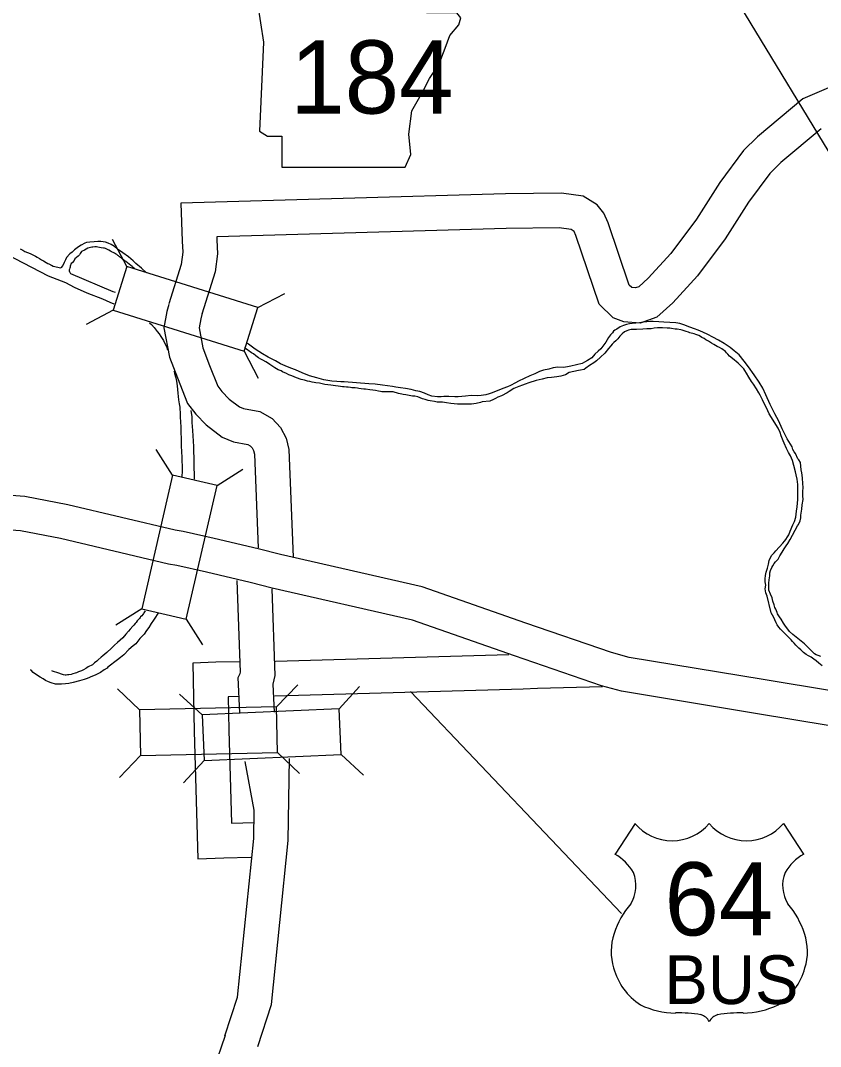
# Model space of a CAD drawing. Extents: x 1720274 to 1751788, y 372074 to 391887.
# Drawn here: x 1725014 to 1726109, y 385389 to 386793 of the extents above; entities that cross this region are included whole.
import ezdxf

# ---------------------------------------------------------------- set-up
doc = ezdxf.new("R2010")
doc.units = 0
for name, color, linetype in [('Level 10', 7, 'Continuous'), ('Level 11', 7, 'Continuous'), ('Level 15', 7, 'Continuous'), ('Level 20', 7, 'Continuous'), ('Level 21', 7, 'Continuous'), ('Level 22', 7, 'Continuous'), ('Level 9', 7, 'Continuous'), ('R_Draft', 7, 'Continuous')]:
    doc.layers.add(name, color=color, linetype=linetype)

msp = doc.modelspace()

# ---------------------------------------------------------------- linework, layer by layer
at = {"layer": 'Level 10'}
for points in [[(1726168.7, 386721.5), (1726084.8, 386685.5), (1726022.8, 386633.5), (1726003.7, 386614.7), (1725971.3, 386571.1), (1725939.5, 386521.1), (1725904, 386473.8), (1725873.4, 386440.2), (1725860.2, 386428.3), (1725856, 386426.8), (1725851, 386427.2), (1725847.2, 386430.8), (1725818.6, 386515.8), (1725812.7, 386529.2), (1725803.4, 386540.4), (1725784.3, 386552.3), (1725754.5, 386556.5), (1725677.9, 386555.5), (1725233.4, 386542.7), (1725235.5, 386490.8), (1725236.1, 386475.7), (1725234, 386458.9), (1725217.2, 386405.2)], [(1726109.9, 386644.7), (1726054.7, 386598.4), (1726039.6, 386583.5), (1726010.3, 386544.2), (1725978.5, 386494.1), (1725940.6, 386443.6), (1725906.9, 386406.6), (1725884.9, 386386.7), (1725862.2, 386378.7), (1725839.9, 386380.5), (1725825.4, 386386.1), (1725806, 386404.6), (1725774.3, 386498.7), (1725772, 386504), (1725771.9, 386504.2), (1725767.7, 386506.8), (1725751.5, 386509), (1725678.9, 386508.1), (1725282.7, 386496.7), (1725282.8, 386492.8), (1725283.6, 386473.7), (1725280.5, 386448.8), (1725262.5, 386391.1)], [(1725217, 386404.2), (1725214.4, 386394.7), (1725210.5, 386372.1), (1725218, 386332.1), (1725228.8, 386303.6), (1725242.6, 386268.5), (1725254, 386254.1), (1725268.2, 386239.3), (1725290.2, 386222.5), (1725305.6, 386216.1), (1725325.3, 386212.5), (1725328.7, 386210.6), (1725331, 386208.1), (1725333.1, 386204.2), (1725334.2, 386199.3), (1725339.4, 386071.2)], [(1725262.8, 386392.1), (1725260.8, 386384.6), (1725258.7, 386372.4), (1725263.8, 386345), (1725273, 386320.6), (1725284.1, 386292.4), (1725289.8, 386285.3), (1725299.8, 386274.8), (1725314.1, 386263.9), (1725319.2, 386261.8), (1725341.7, 386257.6), (1725358.6, 386248.2), (1725370.1, 386235.6), (1725377.8, 386221.1), (1725381.4, 386205.8), (1725387.3, 386058.5)], [(1725314.3, 385845.4), (1725312.1, 385893.6), (1725314.7, 385899.2), (1725315.1, 385901), (1725310.9, 386026.4)], [(1725361.7, 385846.4), (1725360, 385884.7), (1725362.7, 385896.4), (1725358.7, 386015.1)], [(1725251.8, 385820.2), (1725256.7, 385645.5), (1725292.4, 385646.7), (1725329.6, 385647.6)], [(1725299.2, 385821.6), (1725302.8, 385694.3), (1725333.9, 385695.1)], [(1725339.1, 385388.8), (1725357.7, 385446.2), (1725380.7, 385670.6), (1725382.4, 385782.8)], [(1725294, 385403.4), (1725311.1, 385456), (1725333.3, 385673.4), (1725333.9, 385711.9), (1725321.8, 385778.9)], [(1725294.1, 385403.7), (1725278.4, 385357.1), (1725275.9, 385321.8), (1725286.6, 385031.4), (1725290.2, 384925.1), (1725291.3, 384893.1)]]:
    msp.add_lwpolyline(points, dxfattribs=at)
at = {"layer": 'Level 11'}
for points in [[(1725314.4, 385914.9), (1725281.3, 385914.5), (1725249.8, 385913.5), (1725251.8, 385820.4)], [(1725312.9, 385867.5), (1725298.2, 385867.3), (1725299.2, 385821.4)]]:
    msp.add_lwpolyline(points, dxfattribs=at)
at = {"layer": 'Level 15'}
for points in [[(1726544.9, 385908.9), (1726538.4, 385906.8), (1726379.3, 385861.8), (1726334.7, 385854.1), (1726286.7, 385852.8), (1726253, 385855.1), (1726127, 385874.8), (1726030.6, 385890.8), (1725847, 385921.2), (1725823.1, 385927.7), (1725705.9, 385968.2), (1725564, 386017.9), (1725369.9, 386062.2), (1725339.5, 386069.8), (1725279.4, 386083.9), (1725236.8, 386093.7), (1725225.7, 386095.4), (1725079.1, 386130.1), (1725020.3, 386141.6), (1724975.9, 386144.7), (1724941.7, 386143.1), (1724848.3, 386134.7)], [(1726545.5, 385859.6), (1726389.8, 385815.5), (1726339.3, 385806.8), (1726285.7, 385805.4), (1726247.7, 385808), (1726119.5, 385828), (1726022.9, 385844), (1725836.8, 385874.8), (1725809.1, 385882.4), (1725690.3, 385923.4), (1725550.8, 385972.3), (1725358.8, 386016.1), (1725328.4, 386023.7), (1725268.6, 386037.7), (1725227.9, 386047.1), (1725216.7, 386048.8), (1725069.1, 386083.8), (1725014.1, 386094.5), (1724975.3, 386097.3), (1724944.9, 386095.8), (1724852.6, 386087.5)], [(1725363.2, 385916), (1725682.4, 385925.1)], [(1725362.1, 385868.5), (1725702.3, 385878.3), (1725721.6, 385879.1), (1725810.8, 385881.2)]]:
    msp.add_lwpolyline(points, dxfattribs=at)
at = {"layer": 'Level 20'}
for p, q in [((1725159.6, 386456), (1725140.2, 386492.9)), ((1725338.8, 386400), (1725375.7, 386419.4)), ((1725141, 386396.2), (1725104, 386376.9)), ((1725320.1, 386340.3), (1725339.5, 386303.4)), ((1725222.1, 386170.5), (1725200, 386205.9)), ((1725283.1, 386156.5), (1725318.4, 386178.7)), ((1725222.1, 386170.5), (1725180.1, 385987.6)), ((1725283.1, 386156.5), (1725222.1, 386170.5)), ((1725241, 385973.6), (1725283.1, 386156.5)), ((1725180.1, 385987.6), (1725144.7, 385965.5)), ((1725180.1, 385987.6), (1725241, 385973.6)), ((1725241, 385973.6), (1725263.2, 385938.2)), ((1725364.7, 385853.5), (1725393.5, 385883.6)), ((1725450.1, 385850.8), (1725478.3, 385881.5)), ((1725177, 385849.4), (1725146.9, 385878.2)), ((1725262.6, 385842.5), (1725231.9, 385870.7)), ((1725178.4, 385786.8), (1725149.6, 385756.7)), ((1725366.1, 385791), (1725396.2, 385762.1)), ((1725452.9, 385788.3), (1725483.7, 385760.1)), ((1725265.4, 385780), (1725237.2, 385749.3))]:
    msp.add_line(p, q, dxfattribs=at)
for points in [[(1725338.8, 386400), (1725159.6, 386456), (1725141, 386396.2), (1725320.1, 386340.3)], [(1725364.7, 385853.5), (1725177, 385849.4), (1725178.4, 385786.8), (1725366.1, 385791)], [(1725450.1, 385850.8), (1725262.6, 385842.5), (1725265.4, 385780), (1725452.9, 385788.3)]]:
    msp.add_lwpolyline(points, close=True, dxfattribs=at)
at = {"layer": 'Level 21'}
msp.add_lwpolyline([(1725334.6, 386843.2), (1725346.6, 386763), (1725341.3, 386641.3), (1725352, 386634.7), (1725372, 386634.7), (1725372, 386591.9), (1725540.4, 386591.9), (1725548.5, 386609.3), (1725545.8, 386637.3), (1725549.8, 386669.4), (1725564.5, 386694.8), (1725573.9, 386713.5), (1725587.2, 386733.6), (1725595.2, 386755), (1725601.9, 386772.3), (1725614, 386787), (1725616.6, 386796.4), (1725611.3, 386803.1), (1725569.8, 386803.1), (1725579.2, 386821.8), (1725580.5, 386833.8), (1725575, 386843)], close=True, dxfattribs=at)
at = {"layer": 'Level 22'}
for p, q in [((1725547.8, 385874.3), (1725836.9, 385570.7)), ((1725855.2, 385694), (1725827.8, 385651.8)), ((1726058.5, 385694), (1726085.8, 385651.8))]:
    msp.add_line(p, q, dxfattribs=at)
for centre, radius, start, end in [((1725906.1, 385736.9), 66.6, 220.075, 319.6701), ((1726007.6, 385736.9), 66.6, 220.3299, 319.925), ((1725792.1, 385590.4), 71, 30.7809, 59.9883), ((1726121.6, 385590.4), 71, 120.0117, 149.2191), ((1725807.7, 385609.1), 48.7, 328.8105, 21.2108), ((1726105.9, 385609.1), 48.7, 158.7892, 211.1895), ((1725935.1, 385509.3), 113.6, 138.9565, 162.6913), ((1725978.6, 385509.3), 113.6, 17.3087, 41.0435), ((1725897.6, 385518.6), 75.1, 160.9576, 197.3819), ((1726016.1, 385518.6), 75.1, 342.6181, 19.0424), ((1725909.8, 385518.8), 86.9, 195.1074, 237.1312), ((1726003.9, 385518.8), 86.9, 302.8688, 344.8926), ((1725911.4, 385546.1), 111.6, 244.0771, 269.5779), ((1726002.2, 385546.1), 111.6, 270.4221, 295.9229), ((1725914, 385230.3), 204.3, 81.1942, 90.9539), ((1725939.5, 385413.5), 19.6, 28.0342, 72.9864), ((1725974.1, 385413.5), 19.6, 107.0136, 151.9658), ((1725999.7, 385230.3), 204.3, 89.0461, 98.8058)]:
    msp.add_arc(centre, radius, start, end, dxfattribs=at)
at = {"layer": 'Level 9'}
for points in [[(1724946.1, 386498.6), (1724949, 386496.8), (1725052, 386443.4), (1725075.6, 386434.3), (1725087.8, 386428), (1725105, 386420.2), (1725126.2, 386412), (1725136.5, 386407.3), (1725141.9, 386405.1)], [(1725186.8, 386447.7), (1725179.9, 386453.9), (1725172.1, 386460.3), (1725168.2, 386464.1), (1725161.9, 386469.6), (1725154.3, 386474.8), (1725147, 386479.7), (1725142.6, 386483.6), (1725138.1, 386486.4), (1725134.3, 386488.2), (1725130.3, 386489.5), (1725124.3, 386490.4), (1725119.8, 386490.4), (1725115, 386490.1), (1725109, 386489.4), (1725104.6, 386488.8), (1725102.2, 386488.1), (1725097, 386485.4), (1725093.6, 386483.1), (1725088.2, 386478.9), (1725085, 386476), (1725081.6, 386473.5), (1725077.3, 386468.4), (1725075.7, 386465.1), (1725073.8, 386461.5), (1725071.9, 386457.6), (1725069.4, 386454.4)], [(1725170.3, 386453.5), (1725169.7, 386454), (1725168.5, 386454.9), (1725167.1, 386456.3), (1725164.6, 386457.8), (1725163.4, 386458.7), (1725162.7, 386459.5), (1725160.6, 386461.2), (1725158.3, 386462.8), (1725157.3, 386463.6), (1725156.2, 386464.4), (1725153, 386466.9), (1725152.3, 386467.4), (1725149.6, 386469.4), (1725148.4, 386470.6), (1725147.5, 386471.4), (1725146, 386472.4), (1725144.4, 386473.6), (1725142.6, 386474.5), (1725141, 386475.4), (1725138.8, 386476.3), (1725137.3, 386477.2), (1725134.9, 386478.4), (1725132.3, 386479.7), (1725130.4, 386480.8), (1725129.1, 386481.1), (1725127.6, 386481.3), (1725124.5, 386481.9), (1725120.1, 386482.7), (1725118, 386483.1), (1725116.1, 386482.9), (1725113.3, 386482.6), (1725111.7, 386482.4), (1725108.3, 386481.8), (1725106.4, 386481.1), (1725104.1, 386479.9), (1725101.8, 386478.4), (1725097.7, 386476.7), (1725095.9, 386474), (1725094.7, 386472.3), (1725092.9, 386470.4), (1725090.9, 386468.6), (1725088.6, 386466.7), (1725087.4, 386464.5), (1725084.8, 386461.2), (1725083.4, 386460.1), (1725082.3, 386456.6), (1725082, 386455), (1725081.8, 386454.2), (1725081.3, 386452.6), (1725080.9, 386451.8), (1725080.8, 386451), (1725080.8, 386450), (1725081.3, 386448.9), (1725081.5, 386448.6), (1725082, 386447.4), (1725082.5, 386446.6), (1725082.8, 386446.4)], [(1725013.5, 386480.2), (1725017.3, 386478.4), (1725020.2, 386476.9), (1725023.9, 386475.3), (1725027.6, 386473.8), (1725031.1, 386472), (1725034.5, 386470.4), (1725036.9, 386469), (1725040.3, 386466.9), (1725043, 386465.4), (1725045.8, 386463.8), (1725049.3, 386461.7), (1725051.4, 386460.3), (1725052.9, 386459.6), (1725054.6, 386458.7), (1725055.3, 386458.4), (1725056.5, 386457.8), (1725058.9, 386456.7), (1725069.4, 386454.4)], [(1725082.8, 386446.4), (1725140.3, 386422.1), (1725143.5, 386421)], [(1725190.7, 386379), (1725193.5, 386376.8), (1725197.2, 386372.6), (1725201.1, 386367.4), (1725204.1, 386363.8), (1725206.2, 386360.4), (1725208.2, 386357.5), (1725209.7, 386354.8), (1725210.9, 386352.6), (1725212.5, 386349.2), (1725214.3, 386345.5), (1725215.3, 386342.1)], [(1725925, 386367.2), (1725919.8, 386368.9), (1725917.9, 386369.3), (1725912.9, 386370.4), (1725910.1, 386370.5), (1725905.2, 386371.5), (1725902.8, 386371.7), (1725899.2, 386371.9), (1725893, 386372.2), (1725890, 386372.4), (1725885.9, 386372.4), (1725881.5, 386371.8), (1725877.4, 386371), (1725871.4, 386371), (1725865.7, 386370.3), (1725857.1, 386370), (1725852.8, 386369.9), (1725849.7, 386369.8), (1725846.4, 386368.9), (1725843.9, 386367.9), (1725840.9, 386366.7), (1725837.7, 386364.2), (1725834.5, 386360.6), (1725831.6, 386357.2), (1725828.9, 386354.5), (1725826, 386352.1), (1725824.1, 386350), (1725822.1, 386347.8), (1725818.8, 386343.9), (1725813.8, 386337.6), (1725808, 386332.3), (1725802.3, 386327), (1725798.6, 386324.4), (1725792.9, 386320.6), (1725788, 386316.9), (1725785.4, 386315.4), (1725780.5, 386314.1), (1725777.7, 386313.6), (1725765.1, 386310.9), (1725760, 386308.1), (1725753.8, 386306), (1725748.3, 386305), (1725741.1, 386304.3), (1725734.8, 386303.6), (1725728, 386302), (1725719.9, 386300.1), (1725709.9, 386296.8), (1725704.8, 386294.9), (1725701.2, 386293.6), (1725696.2, 386292), (1725689.5, 386289.1), (1725683, 386285.3), (1725680.1, 386283.3), (1725672.3, 386279.2), (1725667.5, 386277.2), (1725664.1, 386275.3), (1725661.3, 386274.1), (1725656.6, 386271.9), (1725646.2, 386270.8), (1725643.7, 386269.9), (1725637.9, 386268.8), (1725631.3, 386267.9), (1725625.2, 386267.7), (1725618.7, 386267.7), (1725612.1, 386267.6), (1725603.2, 386268.7), (1725597.2, 386269.8), (1725591.8, 386270.3), (1725584.5, 386270.7), (1725580.9, 386271.3), (1725574.8, 386272.2), (1725572.1, 386272.8), (1725567.8, 386274.1), (1725564.5, 386275.1), (1725558.1, 386278), (1725553.8, 386278.7), (1725550.8, 386278.9), (1725541.6, 386280.7), (1725538.1, 386281), (1725536, 386281.4), (1725531.7, 386282.3), (1725524.2, 386284.5), (1725512.6, 386284.5), (1725510.7, 386284.7), (1725508.9, 386284.8), (1725506.9, 386284.9), (1725504.2, 386285.5), (1725500, 386286.5), (1725496.5, 386287), (1725492.1, 386287.3), (1725486.3, 386288.1), (1725484.2, 386288.3), (1725480.2, 386288.8), (1725477.4, 386289.2), (1725475.5, 386289.6), (1725472.3, 386290), (1725470.2, 386290.1), (1725467.6, 386290.3), (1725465.7, 386290.6), (1725462.5, 386290.8), (1725460.1, 386291)], [(1726045.8, 386049.7), (1726047.4, 386051.9), (1726051.1, 386055.4), (1726053.6, 386060.2), (1726056.6, 386065.4), (1726059.3, 386069.8), (1726061.9, 386074), (1726064.4, 386077.2), (1726067.6, 386082.7), (1726077.7, 386101.1), (1726078.7, 386103), (1726081.1, 386108), (1726082.2, 386112), (1726082.2, 386115.8), (1726083.4, 386124), (1726084.1, 386129.8), (1726085.2, 386137.2), (1726085, 386142.2), (1726084.8, 386147.8), (1726085.1, 386154.3), (1726084.7, 386158.9), (1726084.5, 386167), (1726083.3, 386173.7), (1726082.7, 386177.7), (1726081.6, 386187.8), (1726079.4, 386191.7), (1726078.2, 386193.1), (1726074.7, 386200.1), (1726073, 386202.4), (1726071, 386205.7), (1726070.1, 386209.3), (1726067.9, 386213.2), (1726063.3, 386220.5), (1726056.7, 386234), (1726051.9, 386244.5), (1726046.7, 386254.6), (1726040.3, 386267.4), (1726034.3, 386280.6), (1726029.9, 386289.6), (1726025.3, 386298), (1726018.4, 386307.9), (1726010.6, 386318.9), (1726004.7, 386326.8), (1725997.7, 386335.3), (1725990.8, 386340.8), (1725985.3, 386345.2), (1725977.2, 386351), (1725969.3, 386355.3), (1725961.9, 386359.5), (1725955, 386363.1), (1725947.8, 386366.2), (1725941.7, 386369), (1725936.4, 386370.7), (1725930.2, 386373.2), (1725922.2, 386376.4), (1725916.6, 386378.3), (1725911.2, 386379.1), (1725902.8, 386379.5), (1725894.8, 386379.8), (1725888, 386380.4), (1725880.2, 386380.8), (1725875.7, 386381), (1725867, 386380), (1725861.5, 386379.2), (1725856.5, 386378.4), (1725851.1, 386378.1), (1725847.7, 386377.5), (1725843.6, 386376.9), (1725839.5, 386375.3), (1725835, 386373.4), (1725830.2, 386370.6), (1725827.4, 386369.2), (1725825.8, 386367.6), (1725824.2, 386365.3), (1725821.8, 386362.6), (1725818.8, 386358.8), (1725815.4, 386352.8), (1725811, 386347.1), (1725808.2, 386343.7), (1725804.7, 386340.4), (1725800.4, 386336.3), (1725795.9, 386331.3), (1725790.2, 386327.6), (1725786.1, 386325.3), (1725782.9, 386323.2), (1725767.2, 386319.7), (1725762.8, 386318.8), (1725757.2, 386318.1), (1725749.6, 386318.2), (1725743, 386317.3), (1725737.4, 386315.7), (1725729.8, 386314.4), (1725724.4, 386312.3), (1725718.3, 386309.4), (1725711.2, 386306.5), (1725703.6, 386302.7), (1725695.9, 386299.3), (1725691.6, 386297), (1725684.6, 386293.4), (1725680.6, 386291.5), (1725674.5, 386289.4)], [(1726077.8, 385935.3), (1726075.2, 385937.9), (1726073.1, 385940.7), (1726070.8, 385942.9), (1726068.8, 385945), (1726066.9, 385947), (1726065.2, 385948.9), (1726062.9, 385951.2), (1726060.5, 385953.6), (1726057.7, 385956.4), (1726054.5, 385959.6), (1726052, 385962.7), (1726049.8, 385965.9), (1726048.3, 385968.7), (1726046.6, 385972.5), (1726045.1, 385975.9), (1726041.7, 385982), (1726041, 385984), (1726036.1, 386004.8), (1726035, 386007.1), (1726034.2, 386009.7), (1726033.5, 386015), (1726034, 386020.1), (1726033.3, 386024.8), (1726033.5, 386028.5), (1726033.9, 386033.4), (1726034.7, 386037.7), (1726036.5, 386043.5), (1726037.9, 386048.9), (1726038.9, 386053.6), (1726040.3, 386057.1), (1726042.6, 386061.1), (1726045.6, 386064.2), (1726048, 386066.9), (1726057.3, 386077.3), (1726059.7, 386080.2), (1726061.7, 386082.5), (1726063.8, 386086.1), (1726065.6, 386089.1), (1726067.7, 386093.8), (1726071.3, 386102.8), (1726073.4, 386107.1), (1726075.1, 386112.9), (1726076.4, 386121.2), (1726077.1, 386127.2), (1726077.6, 386132.2), (1726077.9, 386137.4), (1726077.9, 386141.7), (1726077.9, 386146.8), (1726078, 386152), (1726077.8, 386157.9), (1726077, 386165), (1726075.8, 386171.1), (1726074.7, 386175), (1726072.6, 386183.7), (1726070.6, 386190.8), (1726068, 386197.2), (1726065.3, 386201.5), (1726062.6, 386207.3), (1726059.2, 386214.6), (1726058, 386217.6), (1726055.4, 386224.2), (1726053.7, 386229), (1726051.3, 386234.8), (1726038.9, 386254.6), (1726036.8, 386258.6), (1726034.2, 386264.5), (1726031.7, 386269.5), (1726029.6, 386273.7), (1726026.4, 386280.1), (1726024.7, 386283.1), (1726021.4, 386288.9), (1726017.2, 386295.1), (1726014.7, 386298.8), (1726011.1, 386304.8), (1726007.9, 386310), (1726005.6, 386314), (1726004.1, 386316.2), (1725999.8, 386320.2), (1725996.2, 386323.9), (1725988.4, 386330.3), (1725984.5, 386333.6), (1725982.2, 386336.2), (1725980.3, 386338.2), (1725978.8, 386339.9), (1725973.8, 386343.6), (1725970.9, 386345.2), (1725967.4, 386346.8), (1725963.2, 386349.4), (1725960, 386351.2), (1725955.8, 386353.9), (1725952.2, 386356), (1725950, 386357.5), (1725946.8, 386359.2), (1725945, 386360.2), (1725942.3, 386361.6), (1725938.6, 386363.2), (1725936, 386363.9), (1725930.3, 386365.6), (1725928.2, 386366.3), (1725925, 386367.2)], [(1725460.1, 386291), (1725457.1, 386291.4), (1725456, 386291.5), (1725454.7, 386291.6), (1725452.2, 386292), (1725449, 386292.6), (1725445.4, 386292.9), (1725441.9, 386293.3), (1725438.7, 386293.8), (1725434.8, 386294.3), (1725430.8, 386294.8), (1725426.8, 386295.6), (1725423.3, 386296.3), (1725418.4, 386297.1), (1725416, 386297.5), (1725413.2, 386298), (1725410.3, 386298.7), (1725407, 386299.3), (1725402.8, 386300.4), (1725398.5, 386301.4), (1725392.1, 386303.7), (1725388.5, 386305), (1725385.3, 386306.3), (1725381.4, 386308.1), (1725378.2, 386309.6), (1725372.9, 386312.1), (1725370.8, 386313.2), (1725366.8, 386314.9), (1725362.3, 386317.3), (1725358.3, 386320), (1725355.2, 386322), (1725353.5, 386323.2), (1725349.9, 386325.6), (1725345.7, 386327.9), (1725343, 386329.5), (1725340.1, 386331.3), (1725338.2, 386332.5), (1725336.1, 386334.1), (1725333, 386336.5), (1725330.2, 386338.1), (1725328.5, 386339.2), (1725326.9, 386340.3), (1725324.7, 386341.9), (1725322.6, 386343.4), (1725321.3, 386344.7), (1725320.5, 386345.4)], [(1725674.5, 386289.4), (1725659.9, 386283.3), (1725655.6, 386281.9), (1725650.8, 386280.6), (1725644.5, 386279.6), (1725640.1, 386279.3), (1725631.1, 386279.5), (1725623.2, 386278.9), (1725613.2, 386277.9), (1725608.4, 386277.9), (1725600.2, 386278.1), (1725593.7, 386278.2), (1725589.8, 386278), (1725584.8, 386278), (1725577, 386278.7), (1725572, 386280.4), (1725567.2, 386282.9), (1725560.8, 386284.9), (1725555.4, 386286), (1725548.6, 386287.6), (1725541.1, 386289.4), (1725534.3, 386290.3), (1725528, 386291), (1725523.1, 386291.8), (1725516.4, 386292.8), (1725509.7, 386293.7), (1725499.4, 386295), (1725491.1, 386295.5), (1725457.2, 386298.1), (1725452.6, 386298.4), (1725447.2, 386298.8), (1725440.1, 386299.4), (1725429.5, 386301.1), (1725419.6, 386303.6), (1725414.5, 386305.2), (1725409.7, 386306.7), (1725399.8, 386310.6), (1725390.4, 386314.6), (1725384, 386317.1), (1725376.3, 386320), (1725370.2, 386323.1), (1725363, 386327), (1725353, 386331.9), (1725345.4, 386336.7), (1725335.4, 386343.2), (1725326.1, 386349.7), (1725324.8, 386350.6)], [(1725224.1, 386313.5), (1725224.4, 386312.3), (1725225.1, 386309.7), (1725226.6, 386303.9), (1725227.7, 386299), (1725228.5, 386292.7), (1725229, 386287.6), (1725229.5, 386282.9), (1725230.3, 386273.9), (1725231.4, 386268.3), (1725232, 386263.5), (1725232.7, 386253.5), (1725232.7, 386248.9), (1725233, 386244.3), (1725233.1, 386241.9), (1725233.5, 386238), (1725234.1, 386211.7), (1725234.7, 386201.6), (1725234.8, 386195.9), (1725234.9, 386191), (1725235.2, 386182.1), (1725235.3, 386180.5), (1725235.2, 386178), (1725235.2, 386174.6), (1725235, 386169.9), (1725235.1, 386167.7)], [(1725247.4, 386259.3), (1725248.6, 386250.2), (1725248.8, 386242.8), (1725249.4, 386231.8), (1725250.9, 386210), (1725251.8, 386165.2)], [(1726109.4, 385922.4), (1726106, 385923.9), (1726103, 385924.9), (1726100.9, 385926.2), (1726098.4, 385928.5), (1726095.3, 385931.6), (1726092.6, 385934.2), (1726090.9, 385936.1), (1726087, 385939.9), (1726082.8, 385943.6), (1726077.9, 385947), (1726071.3, 385952.4), (1726066.4, 385956.8), (1726064.1, 385959.6), (1726061.3, 385963.8), (1726058.6, 385968.1), (1726055.3, 385973.3), (1726052.8, 385976.5), (1726050.4, 385980.9), (1726049.7, 385982.6), (1726047.7, 385987), (1726046.5, 385989.6), (1726045.8, 385993.1), (1726044, 385998.1), (1726042.8, 386002.6), (1726040.7, 386007.7), (1726038.5, 386013), (1726038.2, 386016), (1726038.1, 386019.5), (1726038.5, 386022.8), (1726038.9, 386027.4), (1726039.6, 386032.7), (1726039.9, 386036.8), (1726040.4, 386040.1), (1726042.3, 386044.2), (1726044, 386046.4), (1726045.8, 386049.7)], [(1725184.9, 385984.9), (1725183, 385982.2), (1725182.4, 385981.1), (1725181.5, 385980), (1725180, 385978.2), (1725178.6, 385976.7), (1725178, 385975.9), (1725177.1, 385974.6), (1725175.6, 385973), (1725173.9, 385971), (1725172.4, 385969.1), (1725171.2, 385967.6), (1725169.2, 385965.5), (1725168, 385964), (1725164.2, 385959.8), (1725161.8, 385957.1), (1725158.4, 385953.2), (1725154, 385947.9), (1725147, 385941.6), (1725143, 385937.8), (1725138.6, 385933.9), (1725132.4, 385928.1), (1725126.8, 385923.4), (1725124.5, 385921.4), (1725120.6, 385917.9), (1725118.5, 385916.1), (1725115.6, 385913.8), (1725112.5, 385911.2), (1725106.7, 385908.1), (1725104.9, 385906.8), (1725103.4, 385905.8), (1725100.4, 385904.1), (1725097.5, 385902.7), (1725093.7, 385901.4), (1725090.6, 385900.1), (1725089, 385899.5), (1725085.9, 385898.6), (1725083.4, 385897.7), (1725080.4, 385897.4), (1725078.5, 385897.2), (1725076.5, 385897), (1725075.2, 385896.9), (1725072.9, 385897.3), (1725070.1, 385898.2), (1725066.6, 385899.4), (1725058, 385902.4), (1725056.9, 385902.9)], [(1725202.6, 385982.4), (1725201.1, 385979.7), (1725198.8, 385976.3), (1725196.1, 385972.1), (1725192.8, 385967.4), (1725189.7, 385962.3), (1725186.7, 385957.8), (1725183.2, 385953.2), (1725177.7, 385947.2), (1725172, 385939.9), (1725168.3, 385936.9), (1725162.5, 385931.8), (1725155.6, 385924.8), (1725151, 385921), (1725147.1, 385917.7), (1725133.9, 385907.9), (1725132.7, 385906.6), (1725128.5, 385904.1), (1725123.6, 385900.6), (1725116.3, 385896.7), (1725112.7, 385895.3), (1725105.2, 385892.2), (1725101.3, 385891), (1725094.9, 385889.3), (1725086.1, 385886.8)], [(1726111.5, 385909.8), (1726106.8, 385913.1), (1726103.1, 385916.3), (1726100, 385918.6), (1726096.1, 385921.3), (1726092.6, 385923.4), (1726089.5, 385925.2), (1726087.8, 385926.4), (1726085.7, 385928), (1726083.9, 385929.6), (1726081.9, 385931.5), (1726079.6, 385933.6), (1726077.8, 385935.3)], [(1725086.1, 385886.8), (1725080.5, 385885.5), (1725075.8, 385884.8), (1725070.1, 385884.6), (1725066.2, 385884.6), (1725062.2, 385884.6), (1725056.2, 385886.3), (1725052.5, 385887.6), (1725048.5, 385889.7), (1725045, 385891.8), (1725041.1, 385893.9), (1725036.2, 385897.3), (1725031.7, 385900.6), (1725028.6, 385903.7), (1725028, 385904.2)]]:
    msp.add_lwpolyline(points, dxfattribs=at)
at = {"layer": 'R_Draft'}
msp.add_line((1724881.2, 388657.5), (1727375.4, 384541.3), dxfattribs=at)

# ---------------------------------------------------------------- texts
at = {"layer": 'Level 21'}
msp.add_text('184', height=100.11, dxfattribs=at).set_placement((1725383.4, 386665.5))
at = {"layer": 'Level 22'}
for s, height, p in [('64', 100.11, (1725895.5, 385540.7)), ('BUS', 66.74, (1725895.4, 385446.7))]:
    msp.add_text(s, height=height, dxfattribs=at).set_placement(p)

doc.saveas('drawing.dxf')
